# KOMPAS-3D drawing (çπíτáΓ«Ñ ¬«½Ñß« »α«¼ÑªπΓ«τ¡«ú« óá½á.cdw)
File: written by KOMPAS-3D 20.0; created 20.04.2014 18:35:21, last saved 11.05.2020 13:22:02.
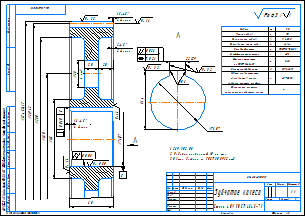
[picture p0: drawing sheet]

Sheet 1: A3, landscape

Document properties: Знак неуказанной шероховатости: 4; Параметр неуказанной шероховатости: Ra 6,3; Полное имя файла: C:\Users\Пользователь\Downloads\Зубчатое колесо промежуточного вала.cdw

Title block, sheet 1: Наименование: Зубчатое колесо; designation: ДМ 413-01.00.11; Материал: Сталь 40Х ГОСТ 4543-71; Количество листов документа: 1; Форматы листов документа: A3; stored path: E:\детали машин мистеркса\Зубчатое колесо промежуточного вала.cdw

Views: Выносной элемент, Вид 3, Вид 6, Вид по стрелке 8, Вид по стрелке А
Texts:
  JS9
  Ra 3,2
  Таблица параметров
  Ra 0,80
  Ra1.6
  Ra 1,6
  Обозначение чертежа
  сопряженного зубчатого колеса
  Радиус развернутости
  эвольвенты в начале
  рабочего участка профиля
  Делительный диаметр
  Степень точности
  по ГОСТ 1643-81
  Коэффициент смещения
  Исходный контур
  Направление линии зуба
  Угол наклона зубьев
  Число зубьев
  Модуль
  ГОСТ 13755-81
  Левое
  Ra 6,3
  Ra 6,3 ( )
  gliv
Dimensions and other numbers on the sheet: 0,026; 22; 81,4; 76; 0,008; 1,6; 4 фаски; 115; 319,63; 324,53; 0,060; 2 фаски; 180; 280; 60; 45,70538; 319,62611; 8-В; -0,3; 9 45'36"; 90; 3,5; 20; 2; 38; 6 отв.; 1; 1:1

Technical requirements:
  1 269...302 HB
  2 Радиусы скруглений 10 мм max.
  3 Общие допуски по ГОСТ 30893.2-тК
